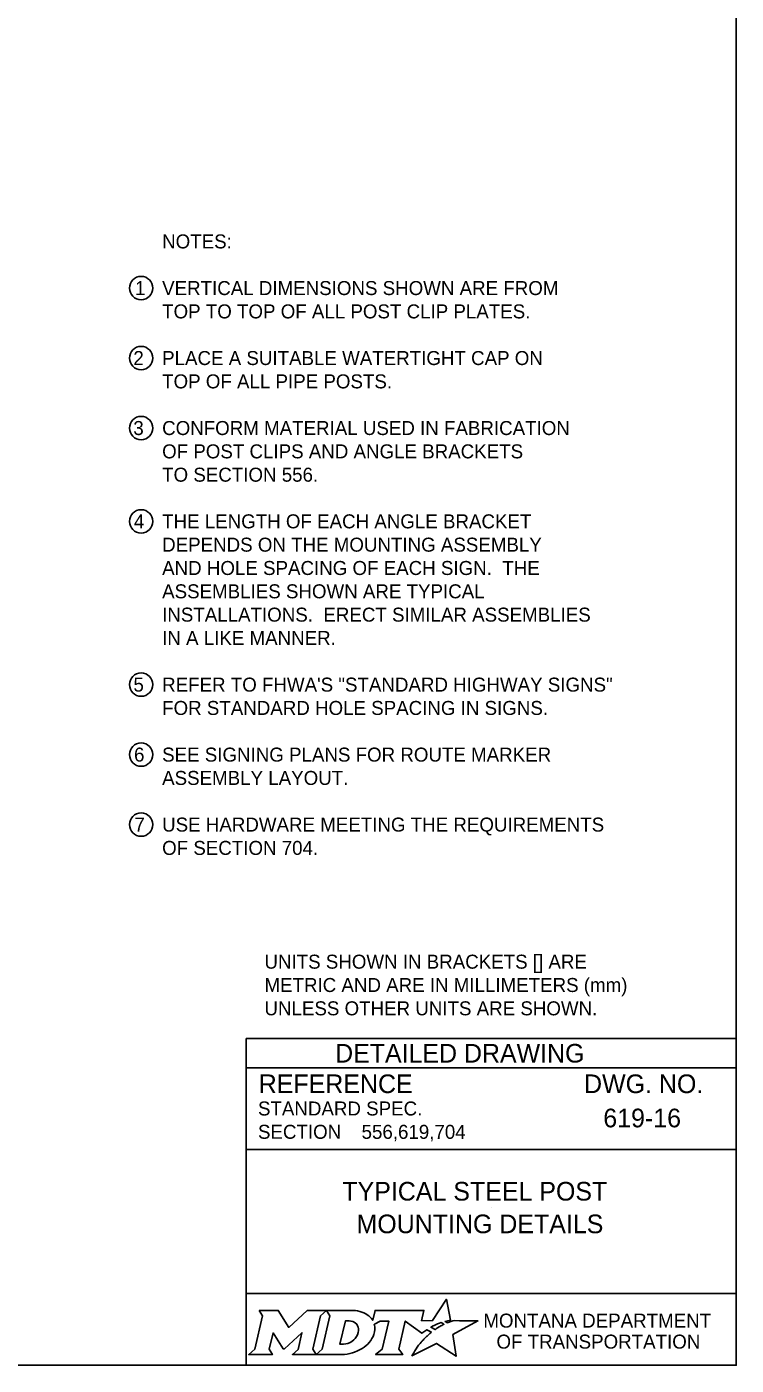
# Model space of a CAD drawing. Extents: x 49991.4 to 50021, y 49987.6 to 50011.4.
# Drawn here: x 50013.71 to 50016.75, y 49987.8 to 49993.54 of the extents above; entities that cross this region are included whole.
import ezdxf

# ---------------------------------------------------------------- set-up
doc = ezdxf.new("R2010")
doc.units = 0
for name, color, linetype in [('Default', 7, 'Continuous'), ('Level 1', 7, 'Continuous'), ('Level 2', 7, 'Continuous'), ('Level 5', 7, 'Continuous')]:
    doc.layers.add(name, color=color, linetype=linetype)

msp = doc.modelspace()

# ---------------------------------------------------------------- linework, layer by layer
at = {"layer": 'Default'}
for points in [[(50015.5126, 49987.9811), (50015.5023, 49987.9867), (50015.5139, 49987.9895), (50015.5255, 49987.9915), (50015.5081, 49988.0816), (50015.4486, 49987.9903), (50015.4013, 49987.9896), (50015.4116, 49988.0337), (50015.2024, 49988.0338), (50015.1923, 49987.9913), (50015.1865, 49987.9996)], [(50014.7056, 49988.0338), (50014.7197, 49988.0104), (50014.6862, 49987.8671), (50014.6605, 49987.8446), (50014.7621, 49987.8446), (50014.7486, 49987.8674), (50014.7648, 49987.9375), (50014.8085, 49987.8685), (50014.8138, 49987.8685), (50014.8889, 49987.938), (50014.8725, 49987.8669), (50014.8478, 49987.8449), (50014.9494, 49987.8449), (50014.9356, 49987.8682), (50014.9688, 49988.0106)], [(50014.9688, 49988.0106), (50014.9941, 49988.0338), (50014.9117, 49988.0338), (50014.8321, 49987.9608), (50014.7876, 49988.0335), (50014.7056, 49988.0338)], [(50015.1077, 49988.0338), (50014.9941, 49988.0338), (50015.0088, 49988.0109), (50014.9749, 49987.8671), (50014.9494, 49987.8449), (50015.06, 49987.8449)], [(50015.1317, 49987.9471), (50015.1305, 49987.939), (50015.1273, 49987.9297), (50015.1231, 49987.9215), (50015.1175, 49987.914), (50015.111, 49987.9071), (50015.1031, 49987.9008), (50015.0948, 49987.8961), (50015.0857, 49987.8922), (50015.0766, 49987.8899), (50015.0674, 49987.889), (50015.0515, 49987.889), (50015.0751, 49987.989), (50015.0911, 49987.989), (50015.0987, 49987.9884), (50015.1063, 49987.9865), (50015.1129, 49987.9835), (50015.119, 49987.9793), (50015.1238, 49987.9743), (50015.1275, 49987.9683), (50015.1302, 49987.9621), (50015.1318, 49987.9547), (50015.1318, 49987.9517), (50015.1317, 49987.9471)], [(50015.1991, 49987.9747), (50015.2237, 49987.9878), (50015.2606, 49987.9878), (50015.232, 49987.8673), (50015.2045, 49987.8446), (50015.3207, 49987.8446), (50015.3037, 49987.8675), (50015.3319, 49987.9877), (50015.4032, 49987.936), (50015.4243, 49987.9511), (50015.444, 49987.9402)], [(50015.3882, 49987.8843), (50015.3729, 49987.8599), (50015.3682, 49987.8524), (50015.3624, 49987.8438), (50015.3601, 49987.8395), (50015.4654, 49987.8926), (50015.5493, 49987.8375), (50015.5362, 49987.9302), (50015.6431, 49987.9886), (50015.5938, 49987.9894), (50015.5637, 49987.9898), (50015.5429, 49987.9901), (50015.5361, 49987.9886), (50015.5312, 49987.9874), (50015.5228, 49987.9851), (50015.5126, 49987.9811)], [(50015.4622, 49987.9535), (50015.4598, 49987.9518), (50015.4415, 49987.9614), (50015.4518, 49987.9671), (50015.4559, 49987.9693), (50015.4645, 49987.9733), (50015.4702, 49987.9759), (50015.4781, 49987.9789), (50015.4854, 49987.9816), (50015.4972, 49987.9742), (50015.4932, 49987.9721), (50015.4886, 49987.9696), (50015.4844, 49987.9674), (50015.4794, 49987.9645), (50015.4775, 49987.9634), (50015.4748, 49987.9618), (50015.4723, 49987.9604), (50015.47, 49987.9588), (50015.4674, 49987.957), (50015.4647, 49987.9552), (50015.4622, 49987.9535)], [(50015.1057, 49987.8522), (50015.1141, 49987.8548), (50015.1271, 49987.8602), (50015.1475, 49987.8712)], [(50015.4021, 49987.9004), (50015.4021, 49987.9004)]]:
    msp.add_lwpolyline(points, dxfattribs=at)
for centre, radius, start, end in [((50015.0868, 49987.9727), 0.1183, 300.91025, 339.13831), ((50015.1308, 49987.9554), 0.0709, 339.53292, 15.85821)]:
    msp.add_arc(centre, radius, start, end, dxfattribs=at)
for centre, major_axis, ratio, start_param, end_param in [((50015.1056, 49987.9864), (0.0834, -0.0037), 0.568097, 0.61298, 1.570796), ((50015.1612, 49987.9937), (0.0361, -0.0295), 0.469099, 1.225588, 1.570796), ((50015.4329, 49987.9305), (-0.0112, -0.0097), 0.021651, 3.157348, 6.283185), ((50015.3952, 49987.8923), (-0.00694, -0.00806), 0.008222, 0, 3.137361), ((50015.4119, 49987.9106), (-0.0098, -0.0102), 0.016458, 3.141593, 6.279097), ((50015.0603, 49987.9932), (0, 0.1484), 0.987302, 3.139398, 3.456847)]:
    msp.add_ellipse(centre, major_axis=major_axis, ratio=ratio, start_param=start_param, end_param=end_param, dxfattribs=at)
at = {"layer": 'Level 1'}
msp.add_lwpolyline([(49999.3835, 49998.9992), (50016.7501, 49998.9992), (50016.7501, 49987.7988), (49999.3835, 49987.7988)], close=True, dxfattribs=at)
at = {"layer": 'Level 2'}
for centre in [(50014.1996, 49992.4165), (50014.1996, 49992.1165), (50014.1996, 49991.8165), (50014.1996, 49991.4165), (50014.1996, 49990.7165), (50014.1996, 49990.4165), (50014.1996, 49990.1165)]:
    msp.add_circle(centre, 0.05, dxfattribs=at)
at = {"layer": 'Level 5'}
for p, q in [((50016.7501, 49989.1988), (50014.6501, 49989.1988)), ((50014.6501, 49989.1988), (50014.6501, 49987.7988)), ((50016.7501, 49989.0738), (50014.6501, 49989.0738)), ((50016.3862, 49988.8587), (50016.3862, 49988.8587)), ((50015.1444, 49988.7993), (50015.1444, 49988.7993)), ((50016.7501, 49988.7238), (50014.6501, 49988.7238)), ((50015.7001, 49988.4747), (50015.7001, 49988.4747)), ((50016.7501, 49988.1057), (50014.6501, 49988.1057))]:
    msp.add_line(p, q, dxfattribs=at)

# ---------------------------------------------------------------- texts
at = {"layer": 'Default'}
for s, p in [('MONTANA DEPARTMENT', (50015.6663, 49987.96)), ('OF TRANSPORTATION', (50015.7225, 49987.87))]:
    msp.add_text(s, height=0.06, dxfattribs=at).set_placement(p)
at = {"layer": 'Level 2'}
for s, height, p in [('NOTES:', 0.06, (50014.2896, 49992.5865)), ('1', 0.06, (50014.1735, 49992.3865)), ('VERTICAL DIMENSIONS SHOWN ARE FROM', 0.06, (50014.2896, 49992.3865)), ('TOP TO TOP OF ALL POST CLIP PLATES.', 0.06, (50014.2896, 49992.2865)), ('2', 0.06, (50014.1663, 49992.0865)), ('PLACE A SUITABLE WATERTIGHT CAP ON', 0.06, (50014.2896, 49992.0865)), ('TOP OF ALL PIPE POSTS.', 0.06, (50014.2896, 49991.9865)), ('3', 0.06, (50014.1662, 49991.7865)), ('CONFORM MATERIAL USED IN FABRICATION', 0.06, (50014.2896, 49991.7865)), ('OF POST CLIPS AND ANGLE BRACKETS', 0.06, (50014.2896, 49991.6865)), ('TO SECTION 556.', 0.06, (50014.2896, 49991.5865)), ('4', 0.06, (50014.1686, 49991.3865)), ('THE LENGTH OF EACH ANGLE BRACKET', 0.06, (50014.2896, 49991.3865)), ('DEPENDS ON THE MOUNTING ASSEMBLY', 0.06, (50014.2896, 49991.2865)), ('AND HOLE SPACING OF EACH SIGN.  THE', 0.06, (50014.2896, 49991.1865)), ('ASSEMBLIES SHOWN ARE TYPICAL ', 0.06, (50014.2896, 49991.0865)), ('INSTALLATIONS.  ERECT SIMILAR ASSEMBLIES', 0.06, (50014.2896, 49990.9865)), ('IN A LIKE MANNER.', 0.06, (50014.2896, 49990.8865)), ('5', 0.06, (50014.1667, 49990.6865)), ('REFER TO FHWA\'S "STANDARD HIGHWAY SIGNS"', 0.06, (50014.2896, 49990.6865)), ('FOR STANDARD HOLE SPACING IN SIGNS. ', 0.06, (50014.2896, 49990.5865)), ('6', 0.06, (50014.1692, 49990.3865)), ('SEE SIGNING PLANS FOR ROUTE MARKER', 0.06, (50014.2896, 49990.3865)), ('ASSEMBLY LAYOUT.', 0.06, (50014.2896, 49990.2865)), ('7', 0.06, (50014.1706, 49990.0865)), ('USE HARDWARE MEETING THE REQUIREMENTS', 0.06, (50014.2896, 49990.0865)), ('OF SECTION 704.', 0.06, (50014.2896, 49989.9865)), ('UNITS SHOWN IN BRACKETS [] ARE ', 0.06, (50014.7282, 49989.4988)), ('METRIC AND ARE IN MILLIMETERS (mm) ', 0.06, (50014.7282, 49989.3988)), ('UNLESS OTHER UNITS ARE SHOWN.', 0.06, (50014.7282, 49989.2988)), ('619-16', 0.08, (50016.1804, 49988.8187)), ('556,619,704', 0.06, (50015.1444, 49988.7693)), ('TYPICAL STEEL POST', 0.08, (50015.0619, 49988.5047)), ('MOUNTING DETAILS', 0.08, (50015.1227, 49988.3647))]:
    msp.add_text(s, height=height, dxfattribs=at).set_placement(p)
at = {"layer": 'Level 5'}
for s, height, p in [('DETAILED DRAWING', 0.0799, (50015.0311, 49989.0963)), ('REFERENCE', 0.08, (50014.7037, 49988.9654)), ('DWG. NO.', 0.08, (50016.0979, 49988.9654)), ('STANDARD SPEC.', 0.06, (50014.7004, 49988.8694)), ('SECTION', 0.06, (50014.7004, 49988.7694))]:
    msp.add_text(s, height=height, dxfattribs=at).set_placement(p)

doc.saveas('drawing.dxf')
